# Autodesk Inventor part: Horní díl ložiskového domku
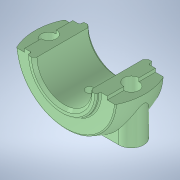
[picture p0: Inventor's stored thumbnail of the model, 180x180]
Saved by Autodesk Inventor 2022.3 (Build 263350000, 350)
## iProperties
Created: 2025-11
Part Number: Horní díl ložiskového domku
Material: Všeobecné
Document SubType Name: Modeling
Designer: Hra42
Density: 1 g/cm^3
Appearance: Výchozí
Sending System: SolidWorks 2012
Last Author: Hra42
Last Saved: 2025-11-14
Author: Hra42
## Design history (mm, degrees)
feature "T_X2_011B_X0_leso1"
fillet "Zaoblení1" dims "d0" = 2.5
node "Těleso1"
